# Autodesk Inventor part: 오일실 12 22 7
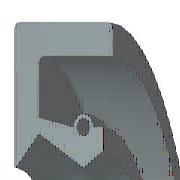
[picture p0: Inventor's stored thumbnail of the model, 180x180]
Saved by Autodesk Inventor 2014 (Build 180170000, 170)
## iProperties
Created: 2012-02
Part Number: 오일실 12 22 7
Material: 일반
Description: 오일-실
Document SubType Name: Modeling
Standard: KS B 2804
Designer: mduedu
Standards Organization: KS
Language: ko-KR
Size Designation: D - 12 22 7
Categories: <MemberInstance><Categories><Category DisplayName="샤프트 부품" InternalName="7f7aeb1f-a693-4053-b835-cee3144e0d98" Mnemonic="SHFT"><Category DisplayName="실링" Intern
Density: 1 g/cm^3
Mass: 1.3482 g
Surface Area: 18.4996 cm^2
Volume: 1.3482 cm^3
Appearance: 기본값
IsCustomPart: 1
Author: mduedu
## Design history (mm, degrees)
revolve "본체" stored, may be unused: angle "d17" = 90 deg
revolve "스프링1" stored, may be unused: angle "d18" = 90 deg
body "Solid1"
sketch "스케치1"
  geometry: L1 (0, 11)-(7, 11); L2 (7, 9.25)-(1.75, 9.25); L3 (1.75, 7.75)-(4.9, 6); L4 (4.9, 6)-(0, 6); L5 (0, 0)-(9.586, 0) reference; L6 (4.9, 6)-(6.3, 6.875); L7 (0, 18)-(0, -3) reference; L8 (-1.941, 0)-(11.507, 0) reference; L9 (4.2, 8.1)-(1.75, 8.59); L10 (1.75, 8.59)-(1.75, 9.25); L11 (0, 11)-(0, 6.088); L12 (4.9, 6)-(0, 6); L13 (1.75, 7.75)-(0.152, 6.028); L14 (7, 11)-(7, 9.25); L15 (5.6, 8.1)-(6.3, 8.1); L16 (6.3, 8.1)-(6.3, 6.875); C1 r 0.455 at (4.9, 8.1); A1 r 0.7 centre (4.9, 8.1) between (5.6, 8.1) and (4.2, 8.1); A2 r 0.088 centre (0.088, 6.088) between (0, 6.088) and (0.152, 6.028); 1 further point
  constraints: 28 end point, 5 horizontal alignment, 5 point on line, 4 point on circle, 4 vertical alignment, 3 centre point, 3 tangent, 2 collinear, 2 horizontal, 2 perpendicular, 1 coincident, 1 parallel
  dimensions: "d0" = 22 diameter of L1 L5 (= SD2); "d1" = 1.75 distance of L1.end L2.start (= SD); "d2" = 0.91 diameter of C1 (= SPDI); "d3" = 1.4 diameter of A1 (= SPDA); "d4" = 12 diameter of L3.end L5 (= NND); "d5" = 15.5 diameter of L3.start L5 (= TKDM); "d7" = 17.18 diameter of L9.end L5 (= TKDM + 0.24 x SWDT); "d8" = 1.75 distance between parallel lines of L11 L10 (= SD); "d9" = 4.9 distance from line of L11 C1.centre (= SPDST); "d10" = 16.2 diameter of C1.centre L5 (= HLDM); "d11" = 0.0875 radius of A2 (= 0.25 x LAB); "d12" = 6.3 distance between parallel lines of L11 L16 (= SDI); "d13" = 13.75 diameter of L6.end L5 (= ABDM); "d14" = 7 distance from line of L11 L1.end (= SWDT)
fillet "모깎기1" dims "d6" = 0.3 (= RR)
other parameters: "SD2" = 22 [user parameter; used in 1 equation term], "SWDT" = 7 [user parameter; used in 2 equation terms], "RR" = 0.3 [user parameter; used in 1 equation term], "SD" = 1.75 [user parameter; used in 2 equation terms], "NND" = 12 [user parameter; used in 1 equation term], "SPDA" = 1.4 [user parameter; used in 1 equation term], "SPDI" = 0.91 [user parameter; used in 1 equation term], "TKDM" = 15.5 [user parameter; used in 2 equation terms], "HLDM" = 16.2 [user parameter; used in 1 equation term], "ABDM" = 13.75 [user parameter; used in 1 equation term], "SDI" = 6.3 [user parameter; used in 1 equation term], "SPDST" = 4.9 [user parameter; used in 1 equation term], "LAB" = 0.35 [user parameter; used in 1 equation term], "d15" = 0, "d16" = 0, "d19" = 0
